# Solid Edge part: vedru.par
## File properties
Username: Kasutaja
Author: Kasutaja
Template: Iso Metric Part.par
Last saved by: Kasutaja
Revision: 4
Application: Solid Edge
Accuracy: 0,990
Face Style: Model Default
Fill Style: Normal
Coef. of Thermal Exp: 0.0
Thermal Conductivity: 0.0
Specific Heat: 0.0
Modulus of Elasticity: 0.0
Poisson's Ratio: 0.0
Yield Stress: 0.0
Ultimate Stress: 0.0
Elongation: 0.0
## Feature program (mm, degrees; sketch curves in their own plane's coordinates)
helix protrusion "HelixProtrusion_1"  NumberOfTurns = 10
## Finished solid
Body 1: solid body, 3 faces, 2 edges, 0 vertices.
  Faces by surface: plane 2, spline 1
  Edges by curve: circle 2
Bounding box of the edges (mm; curved faces can reach further): 449.000 x 0.000 x 4.000, from (-728.5504, 0, 303.9917) to (-279.5504, 0, 307.9917).
Planar faces by outward normal: +y 1, -y 1
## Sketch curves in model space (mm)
line (-282.9715, 0, 319.3065) -> (-727.9715, 0, 319.3065)
circle centre (-726.5504, 0, 305.9917) radius 2
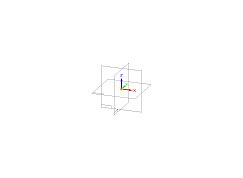
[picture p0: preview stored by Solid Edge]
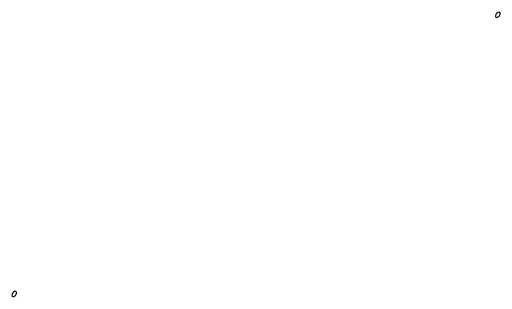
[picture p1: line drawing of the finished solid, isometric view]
